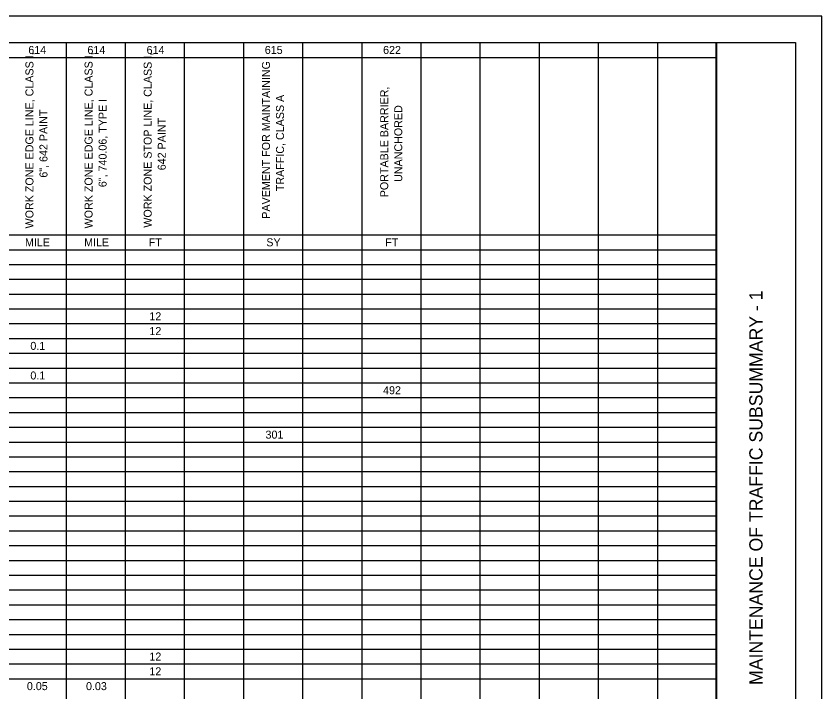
# Model space of a CAD drawing. Extents: x -0.1 to 37.6, y 0 to 22.
# Drawn here: x 18.61 to 33.88, y 9.19 to 21.98 of the extents above; entities that cross this region are included whole.
import ezdxf

# ---------------------------------------------------------------- set-up
doc = ezdxf.new("R2010")
doc.units = 0
for name, color, linetype in [('Default', 7, 'Continuous'), ('SH_Border', 7, 'Continuous'), ('SH_Cut_Line', 7, 'Continuous'), ('SH_Data', 7, 'Continuous')]:
    doc.layers.add(name, color=color, linetype=linetype)

msp = doc.modelspace()

# ---------------------------------------------------------------- linework, layer by layer
at = {"layer": 'Default'}
for p, q in [((1.376, 21.475), (31.879, 21.475)), ((19.559, 21.475), (19.559, 0.475)), ((20.679, 21.475), (20.679, 0.475)), ((21.799, 21.475), (21.799, 0.475)), ((22.919, 21.475), (22.919, 0.475)), ((24.039, 21.475), (24.039, 0.475)), ((25.159, 21.475), (25.159, 0.475)), ((26.279, 21.475), (26.279, 0.475)), ((27.399, 21.475), (27.399, 0.475)), ((28.519, 21.475), (28.519, 0.475)), ((29.639, 21.475), (29.639, 0.475)), ((30.759, 21.475), (30.759, 0.475)), ((31.879, 21.475), (31.879, 0.475)), ((8.359, 21.195), (31.879, 21.195)), ((8.359, 17.835), (31.879, 17.835)), ((1.376, 17.555), (31.879, 17.555)), ((1.376, 17.275), (31.879, 17.275)), ((1.376, 16.995), (31.879, 16.995)), ((1.376, 16.715), (31.879, 16.715)), ((1.376, 16.435), (31.879, 16.435)), ((1.376, 16.155), (31.879, 16.155)), ((1.376, 15.875), (31.879, 15.875)), ((1.376, 15.595), (31.879, 15.595)), ((1.376, 15.315), (31.879, 15.315)), ((1.376, 15.035), (31.879, 15.035)), ((1.376, 14.755), (31.879, 14.755)), ((1.376, 14.475), (31.879, 14.475)), ((1.376, 14.195), (31.879, 14.195)), ((1.376, 13.915), (31.879, 13.915)), ((1.376, 13.635), (31.879, 13.635)), ((1.376, 13.355), (31.879, 13.355)), ((1.376, 13.075), (31.879, 13.075)), ((1.376, 12.795), (31.879, 12.795)), ((1.376, 12.515), (31.879, 12.515)), ((1.376, 12.235), (31.879, 12.235)), ((1.376, 11.955), (31.879, 11.955)), ((1.376, 11.675), (31.879, 11.675)), ((1.376, 11.395), (31.879, 11.395)), ((1.376, 11.115), (31.879, 11.115)), ((1.376, 10.835), (31.879, 10.835)), ((1.376, 10.555), (31.879, 10.555)), ((1.376, 10.275), (31.879, 10.275)), ((1.376, 9.995), (31.879, 9.995)), ((1.376, 9.715), (31.879, 9.715)), ((1.376, 9.435), (31.879, 9.435))]:
    msp.add_line(p, q, dxfattribs=at)
at = {"layer": 'SH_Border'}
msp.add_line((31.876, 0.475), (31.876, 21.475), dxfattribs=at)
msp.add_lwpolyline([(1.376, 21.475), (33.376, 21.475), (33.376, 0.475), (1.376, 0.475)], close=True, dxfattribs=at)
at = {"layer": 'SH_Cut_Line'}
msp.add_lwpolyline([(-0.124, -0.025), (33.876, -0.025), (33.876, 21.975), (-0.124, 21.975)], close=True, dxfattribs=at)

# ---------------------------------------------------------------- texts
at = {"layer": 'Default'}
for s, p in [('614', (18.845, 21.259)), ('614', (19.965, 21.259)), ('614', (21.085, 21.259)), ('615', (23.324, 21.259)), ('622', (25.565, 21.259)), ('MILE', (18.782, 17.619)), ('MILE', (19.902, 17.619)), ('FT', (21.125, 17.619)), ('SY', (23.353, 17.619)), ('FT', (25.605, 17.619)), ('12', (21.138, 16.219)), ('12', (21.138, 15.939)), ('0.1', (18.884, 15.659)), ('0.1', (18.884, 15.099)), ('492', (25.565, 14.819)), ('301', (23.338, 13.979)), ('12', (21.138, 9.779)), ('12', (21.138, 9.499)), ('0.05', (18.818, 9.219)), ('0.03', (19.938, 9.219))]:
    msp.add_text(s, height=0.1515, dxfattribs=at).set_placement(p)
for s, height, p in [('WORK ZONE EDGE LINE, CLASS I, ', 0.15153, (18.942, 17.957)), ('WORK ZONE EDGE LINE, CLASS I, ', 0.15153, (20.062, 17.957)), ('WORK ZONE STOP LINE, CLASS I, ', 0.15153, (21.182, 17.971)), ('PAVEMENT FOR MAINTAINING ', 0.15153, (23.422, 18.141)), ('PORTABLE BARRIER, ', 0.15153, (25.662, 18.547)), ('TRAFFIC, CLASS A', 0.15153, (23.688, 18.662)), ('6", 740.06, TYPE I', 0.15153, (20.328, 18.738)), ('6", 642 PAINT', 0.15153, (19.208, 18.918)), ('UNANCHORED', 0.1515, (25.928, 18.837)), ('642 PAINT', 0.1515, (21.448, 19.058))]:
    msp.add_text(s, height=height, rotation=90, dxfattribs=at).set_placement(p)
at = {"layer": 'SH_Data'}
msp.add_text('MAINTENANCE OF TRAFFIC SUBSUMMARY - 1', height=0.25, rotation=90, dxfattribs=at).set_placement((32.751, 9.317))

doc.saveas('drawing.dxf')
